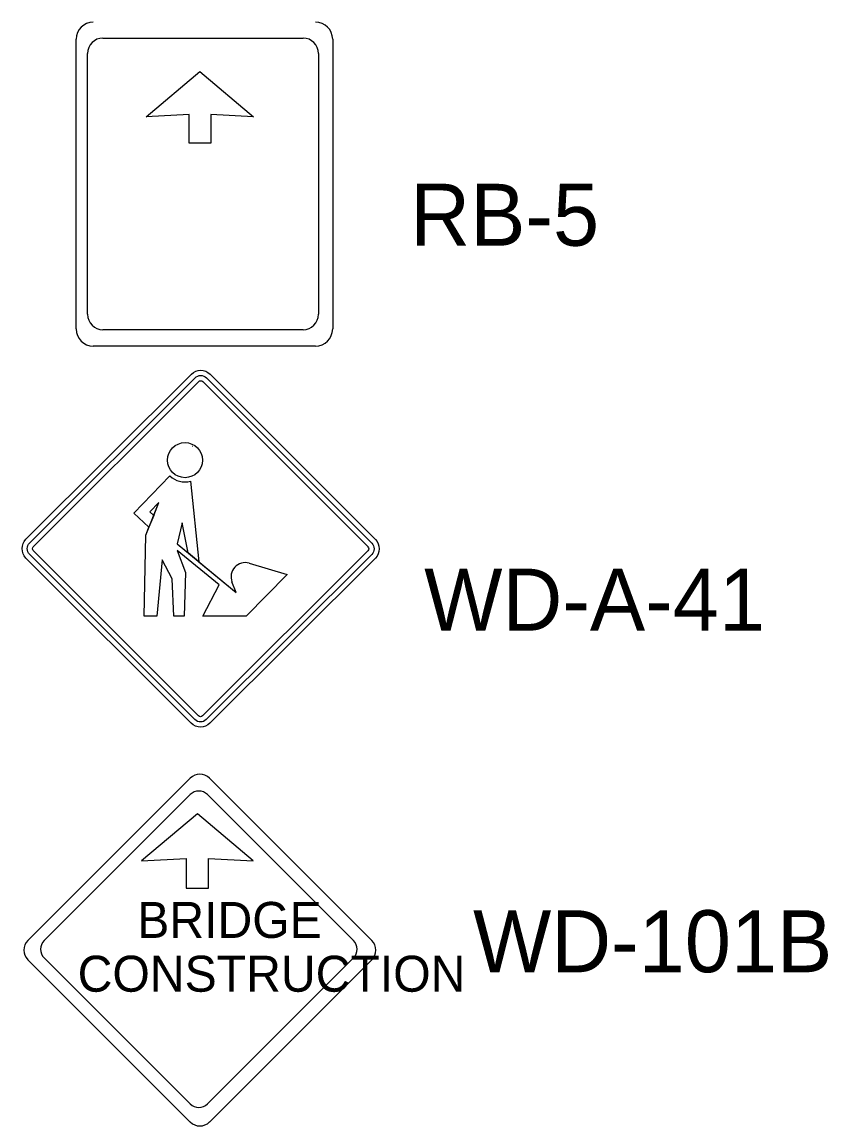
# Model space of a CAD drawing. Extents: x 2157 to 2399, y 147 to 426.
# Drawn here: x 2245.3 to 2272.48, y 200.78 to 238.01 of the extents above; entities that cross this region are included whole.
import ezdxf

# ---------------------------------------------------------------- set-up
doc = ezdxf.new("R2010")
doc.units = 0
for name, color, linetype in [('Level 1', 7, 'Continuous'), ('Level 10', 7, 'Continuous'), ('Level 44', 7, 'Continuous')]:
    doc.layers.add(name, color=color, linetype=linetype)

# ---------------------------------------------------------------- blocks, each defined once
blk = doc.blocks.new('2_95')
at = {"layer": 'Level 1'}
for points in [[(18.2, 120.1), (22.8, 116.1), (17.2, 102.4), (0, 118.7), (41.5, 161.7)], [(18.2, 120.1), (22.8, 116.1), (17.2, 102.4), (0, 118.7), (41.5, 161.7)], [(32.4, 65), (26.3, 0), (11.7, 0), (13.7, 93.4), (17.3, 102.4), (0, 118.7), (41.5, 161.7)], [(65.4, 155.5), (75, 62.6), (62.6, 72.8), (55.6, 107.5), (49.8, 83.3), (117.7, 27.3), (113, 39.4)], [(65.4, 155.5), (75, 62.6), (62.6, 72.8), (55.6, 107.5), (49.8, 83.3), (117.7, 27.3), (113, 39.4)], [(65.4, 155.5), (75, 62.5), (117.7, 27.3), (113, 39.4)], [(132.9, 60.9), (176.6, 47.8), (129.3, 0), (79.5, 0), (98.2, 36), (49.8, 75.6), (59.3, 50.4), (58, 0), (46.2, 0), (44, 43), (32.4, 65), (26.3, 0), (11.7, 0), (13.7, 93.4), (28.7, 130.9), (18.2, 120.1)], [(132.9, 60.9), (176.6, 47.8), (129.3, 0), (79.5, 0), (98.2, 36), (49.8, 75.6), (59.3, 50.4), (58, 0), (46.2, 0), (44, 43), (32.4, 65), (26.3, 0), (11.7, 0), (13.7, 93.4), (28.7, 130.9), (18.2, 120.1)], [(132.9, 60.9), (176.6, 47.8), (129.3, 0), (79.5, 0), (98.2, 36), (49.8, 75.6), (59.3, 50.4), (58, 0), (46.2, 0), (44, 43), (32.4, 65)]]:
    blk.add_lwpolyline(points, dxfattribs=at)
for points in [[(18.2, 120.1), (22.8, 116.1), (28.7, 130.9)], [(62.6, 72.8), (55.6, 107.5), (49.8, 83.3)]]:
    blk.add_lwpolyline(points, close=True, dxfattribs=at)
blk.add_circle((58.9, 179.8), 20.2, dxfattribs=at)
blk.add_circle((58.9, 179.8), 20.2, dxfattribs=at)
blk.add_circle((58.9, 179.8), 20.2, dxfattribs=at)
for centre, radius, start, end in [((58.9, 179.8), 25.1, 226.3135, 284.9576), ((58.9, 179.8), 25.1, 226.3135, 284.9576), ((58.9, 179.8), 25.1, 226.3135, 284.9576), ((128.2, 45.3), 16.3, 73.381, 201.0999), ((128.2, 45.3), 16.3, 73.381, 201.0999), ((128.2, 45.3), 16.3, 73.381, 201.0999)]:
    blk.add_arc(centre, radius, start, end, dxfattribs=at)
blk = doc.blocks.new('WDA41')
at = {"layer": 'Level 1'}
for p, q in [((-6.546, 0.348), (-0.352, 6.542)), ((-6.408, 0.21), (-0.215, 6.404)), ((-6.271, 0.073), (-0.077, 6.267)), ((0.072, 6.267), (6.27, 0.077)), ((0.21, 6.405), (6.408, 0.214)), ((0.348, 6.543), (6.545, 0.352)), ((0.287, 3.829), (0.303, 3.829)), ((-0.348, -6.542), (-6.546, -0.352)), ((-0.211, -6.404), (-6.408, -0.214)), ((-0.073, -6.266), (-6.27, -0.076)), ((6.27, -0.072), (0.076, -6.266)), ((6.408, -0.21), (0.214, -6.404)), ((6.546, -0.348), (0.352, -6.542))]:
    blk.add_line(p, q, dxfattribs=at)
for centre, radius, start, end in [((-0.002, 6.192), 0.495, 45.0349, 135), ((-0.002, 6.192), 0.3, 45.0349, 135), ((-0.002, 6.192), 0.105, 45.0349, 135), ((-6.196, -0.002), 0.495, 135, 225.0349), ((-6.196, -0.002), 0.3, 135, 225.0349), ((-6.196, -0.002), 0.105, 135, 225.0349), ((6.195, 0.002), 0.105, 315, 45.035), ((6.195, 0.002), 0.3, 315, 45.035), ((6.195, 0.002), 0.495, 315, 45.035), ((0.002, -6.192), 0.495, 225.0348, 315), ((0.002, -6.192), 0.3, 225.0348, 315), ((0.002, -6.192), 0.105, 225.0348, 315)]:
    blk.add_arc(centre, radius, start, end, dxfattribs=at)
at = {"layer": 'Level 1', "xscale": 0.032498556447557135, "yscale": -0.032498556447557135, "rotation": 180}
blk.add_blockref('2_95', (2.5, -2.524), dxfattribs=at)

msp = doc.modelspace()

# ---------------------------------------------------------------- linework, layer by layer
at = {"layer": 'Level 44'}
for p, q in [((2247.123, 227.659), (2247.123, 237.43)), ((2248.028, 237.469), (2254.775, 237.469)), ((2255.776, 237.43), (2255.776, 227.659)), ((2247.509, 228.154), (2247.509, 236.948)), ((2255.296, 236.948), (2255.296, 228.154)), ((2247.509, 228.152), (2247.509, 228.154)), ((2247.123, 227.656), (2247.123, 227.659)), ((2254.775, 227.632), (2248.028, 227.632)), ((2255.196, 227.078), (2247.7, 227.078)), ((2250.974, 212.5), (2245.496, 207.031)), ((2257.091, 207.031), (2251.622, 212.5)), ((2246.045, 207.026), (2250.974, 211.949)), ((2251.557, 211.949), (2256.48, 207.026)), ((2251.216, 211.303), (2249.333, 209.717)), ((2253.097, 209.717), (2251.216, 211.303)), ((2249.333, 209.717), (2250.838, 209.798)), ((2250.838, 209.798), (2250.838, 208.793)), ((2251.593, 208.793), (2251.593, 209.798)), ((2251.593, 209.798), (2253.097, 209.717)), ((2250.838, 208.793), (2251.588, 208.793)), ((2245.496, 206.381), (2250.974, 200.906)), ((2245.501, 206.381), (2245.496, 206.381)), ((2250.974, 201.515), (2246.045, 206.442)), ((2256.48, 206.442), (2251.557, 201.515)), ((2251.622, 200.906), (2257.091, 206.381))]:
    msp.add_line(p, q, dxfattribs=at)
msp.add_lwpolyline([(2249.489, 234.814), (2251.298, 236.337), (2253.108, 234.814), (2251.661, 234.89), (2251.661, 233.925), (2250.937, 233.925), (2250.937, 234.89)], close=True, dxfattribs=at)
for centre, radius, start, end in [((2247.702, 237.429), 0.578, 90, 180), ((2255.197, 237.429), 0.578, 360, 90), ((2248.029, 236.947), 0.52, 90, 180), ((2254.775, 236.947), 0.52, 360, 90), ((2248.029, 228.152), 0.52, 180, 270), ((2254.775, 228.152), 0.52, 270, 360), ((2247.702, 227.657), 0.578, 180, 270), ((2255.197, 227.657), 0.578, 270, 360), ((2251.297, 212.178), 0.458, 45, 135), ((2251.264, 211.659), 0.412, 45, 135), ((2245.824, 206.706), 0.458, 135, 225), ((2246.339, 206.733), 0.412, 135, 225), ((2256.19, 206.733), 0.412, 315, 45), ((2256.769, 206.706), 0.458, 315, 45), ((2251.264, 201.808), 0.412, 225, 315), ((2251.297, 201.233), 0.458, 225, 315)]:
    msp.add_arc(centre, radius, start, end, dxfattribs=at)

# ---------------------------------------------------------------- block references
at = {"layer": 'Level 1', "xscale": 0.9, "yscale": -0.9, "rotation": 180}
msp.add_blockref('WDA41', (2251.323, 220.244), dxfattribs=at)

# ---------------------------------------------------------------- texts
at = {"layer": 'Level 10'}
for s, p in [('RB-5', (2258.392, 230.464)), ('WD-A-41', (2258.862, 217.481)), ('WD-101B', (2260.509, 205.959))]:
    msp.add_text(s, height=2.09, dxfattribs=at).set_placement(p)
at = {"layer": 'Level 44'}
for s, height, p in [('BRIDGE', 1.214, (2249.185, 207.116)), ('CONSTRUCTION', 1.21397, (2247.175, 205.302))]:
    msp.add_text(s, height=height, rotation=360, dxfattribs=at).set_placement(p)

doc.saveas('drawing.dxf')
